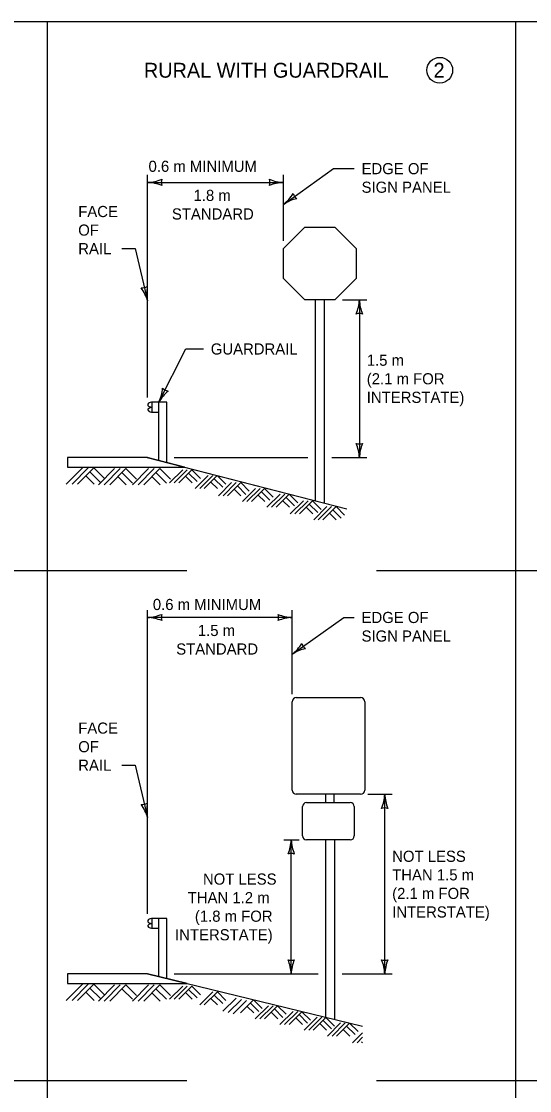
# Model space of a CAD drawing. Extents: x 49991.4 to 50021, y 49987.6 to 50011.4.
# Drawn here: x 50003.09 to 50005.83, y 49993.24 to 49999 of the extents above; entities that cross this region are included whole.
import ezdxf

# ---------------------------------------------------------------- set-up
doc = ezdxf.new("R2010")
doc.units = 0
for name, color, linetype in [('Level 1', 7, 'Continuous'), ('Level 2', 7, 'Continuous'), ('Level 3', 7, 'Continuous')]:
    doc.layers.add(name, color=color, linetype=linetype)

msp = doc.modelspace()

# ---------------------------------------------------------------- linework, layer by layer
at = {"layer": 'Level 1'}
for p, q in [((50004.6721, 49996.4167), (50004.6721, 49997.4987)), ((50004.7207, 49996.4043), (50004.7207, 49997.4987)), ((50003.8291, 49996.948), (50003.7885, 49996.948)), ((50003.7903, 49996.948), (50003.7903, 49996.8947)), ((50003.8291, 49996.6327), (50003.8291, 49996.948)), ((50003.872, 49996.948), (50003.8291, 49996.948)), ((50003.872, 49996.6219), (50003.872, 49996.948)), ((50003.7885, 49996.8947), (50003.8291, 49996.8947)), ((50003.768, 49996.649), (50003.336, 49996.649)), ((50003.336, 49996.649), (50003.336, 49996.5973)), ((50003.7649, 49996.649), (50003.336, 49996.649)), ((50003.336, 49996.649), (50003.336, 49996.5973)), ((50003.7649, 49996.649), (50004.8425, 49996.3731)), ((50003.9668, 49996.5973), (50003.7649, 49996.649)), ((50003.3298, 49996.5067), (50003.4171, 49996.5941)), ((50003.336, 49996.5973), (50003.9668, 49996.5973)), ((50003.336, 49996.5973), (50003.9668, 49996.5973)), ((50003.3605, 49996.5067), (50003.4478, 49996.5941)), ((50003.3909, 49996.5067), (50003.4782, 49996.5941)), ((50003.4568, 49996.5725), (50003.5135, 49996.5158)), ((50003.4782, 49996.5941), (50003.5351, 49996.5373)), ((50003.5026, 49996.5031), (50003.5899, 49996.5904)), ((50003.5333, 49996.5031), (50003.6206, 49996.5904)), ((50003.5637, 49996.5031), (50003.6511, 49996.5904)), ((50003.6295, 49996.5688), (50003.6862, 49996.5122)), ((50003.6511, 49996.5904), (50003.7079, 49996.5337)), ((50003.6861, 49996.5031), (50003.7734, 49996.5904)), ((50003.7168, 49996.5031), (50003.8041, 49996.5904)), ((50003.7472, 49996.5031), (50003.8346, 49996.5904)), ((50003.813, 49996.5688), (50003.8697, 49996.5122)), ((50003.8346, 49996.5904), (50003.8914, 49996.5337)), ((50003.8863, 49996.5126), (50003.957, 49996.5833)), ((50003.9112, 49996.5126), (50003.9819, 49996.5833)), ((50003.9358, 49996.5126), (50004.0065, 49996.5833)), ((50003.9665, 49996.5973), (50003.9665, 49996.5973)), ((50003.9665, 49996.5973), (50003.9665, 49996.5973)), ((50003.9668, 49996.5973), (50004.8425, 49996.3731)), ((50003.9891, 49996.5659), (50004.0352, 49996.52)), ((50004.0065, 49996.5833), (50004.0526, 49996.5373)), ((50003.4351, 49996.5508), (50003.4792, 49996.5067)), ((50003.6079, 49996.5471), (50003.652, 49996.5031)), ((50003.7914, 49996.5471), (50003.8355, 49996.5031)), ((50003.9716, 49996.5483), (50004.0075, 49996.5126)), ((50004.0238, 49996.4819), (50004.0945, 49996.5526)), ((50004.0486, 49996.4819), (50004.1193, 49996.5526)), ((50004.0732, 49996.4819), (50004.1435, 49996.552)), ((50004.109, 49996.5175), (50004.1449, 49996.4819)), ((50004.1266, 49996.5352), (50004.1726, 49996.4893)), ((50004.145, 49996.5517), (50004.19, 49996.5066)), ((50004.1495, 49996.4436), (50004.2202, 49996.5143)), ((50004.1744, 49996.4436), (50004.2451, 49996.5143)), ((50004.199, 49996.4436), (50004.2697, 49996.5143)), ((50004.2697, 49996.5143), (50004.3158, 49996.4683)), ((50004.2348, 49996.4793), (50004.2706, 49996.4436)), ((50004.2524, 49996.4969), (50004.2983, 49996.451)), ((50004.2786, 49996.4118), (50004.3493, 49996.4826)), ((50004.3035, 49996.4118), (50004.3743, 49996.4826)), ((50004.3282, 49996.4118), (50004.3989, 49996.4826)), ((50004.3639, 49996.4474), (50004.3997, 49996.4118)), ((50004.3814, 49996.4651), (50004.4274, 49996.4192)), ((50004.3989, 49996.4826), (50004.445, 49996.4365)), ((50004.4114, 49996.3813), (50004.4821, 49996.452)), ((50004.4362, 49996.3813), (50004.5071, 49996.452)), ((50004.461, 49996.3813), (50004.5317, 49996.452)), ((50004.5317, 49996.452), (50004.5778, 49996.4062)), ((50004.4967, 49996.417), (50004.5324, 49996.3813)), ((50004.5142, 49996.4346), (50004.5602, 49996.3889)), ((50004.5369, 49996.3456), (50004.6076, 49996.4164)), ((50004.5619, 49996.3456), (50004.6326, 49996.4164)), ((50004.5864, 49996.3456), (50004.6571, 49996.4164)), ((50004.6396, 49996.3989), (50004.6857, 49996.353)), ((50004.6571, 49996.4164), (50004.7033, 49996.3703)), ((50004.6631, 49996.3145), (50004.7338, 49996.3852)), ((50004.688, 49996.3145), (50004.7588, 49996.3852)), ((50004.7126, 49996.3145), (50004.7834, 49996.3852)), ((50004.7834, 49996.3852), (50004.8295, 49996.3393)), ((50004.6221, 49996.3813), (50004.6579, 49996.3456)), ((50004.7485, 49996.3502), (50004.7842, 49996.3145)), ((50004.766, 49996.3678), (50004.812, 49996.3219)), ((50004.5694, 49995.3563), (50004.9155, 49995.3563)), ((50004.5469, 49994.8576), (50004.5469, 49995.3338)), ((50004.938, 49995.3338), (50004.938, 49994.8576)), ((50004.9155, 49994.8351), (50004.5694, 49994.8351)), ((50004.728, 49994.7902), (50004.728, 49994.8351)), ((50004.7742, 49994.7902), (50004.7742, 49994.8351)), ((50004.6245, 49994.7902), (50004.8605, 49994.7902)), ((50004.603, 49994.611), (50004.603, 49994.7687)), ((50004.882, 49994.7687), (50004.882, 49994.611)), ((50004.8605, 49994.5895), (50004.6245, 49994.5895)), ((50004.728, 49993.6337), (50004.728, 49994.5895)), ((50004.7766, 49993.6218), (50004.7766, 49994.5895)), ((50003.829, 49994.1664), (50003.7884, 49994.1664)), ((50003.7902, 49994.1664), (50003.7902, 49994.1131)), ((50003.829, 49993.8511), (50003.829, 49994.1664)), ((50003.8719, 49994.1664), (50003.829, 49994.1664)), ((50003.8719, 49993.8403), (50003.8719, 49994.1664)), ((50003.7884, 49994.1131), (50003.829, 49994.1131)), ((50003.768, 49993.8673), (50003.336, 49993.8673)), ((50003.336, 49993.8673), (50003.336, 49993.8156)), ((50003.768, 49993.8673), (50003.336, 49993.8673)), ((50003.336, 49993.8673), (50003.336, 49993.8156)), ((50003.768, 49993.8673), (50004.9267, 49993.5853)), ((50003.9804, 49993.8156), (50003.768, 49993.8673)), ((50003.3299, 49993.725), (50003.4172, 49993.8124)), ((50003.336, 49993.8156), (50003.9804, 49993.8156)), ((50003.336, 49993.8156), (50003.9804, 49993.8156)), ((50003.3605, 49993.725), (50003.4479, 49993.8124)), ((50003.391, 49993.725), (50003.4783, 49993.8124)), ((50003.4783, 49993.8124), (50003.5352, 49993.7556)), ((50003.5027, 49993.7214), (50003.59, 49993.8087)), ((50003.5334, 49993.7214), (50003.6207, 49993.8087)), ((50003.5638, 49993.7214), (50003.6511, 49993.8087)), ((50003.6511, 49993.8087), (50003.708, 49993.752)), ((50003.6862, 49993.7214), (50003.7735, 49993.8087)), ((50003.7169, 49993.7214), (50003.8042, 49993.8087)), ((50003.7473, 49993.7214), (50003.8346, 49993.8087)), ((50003.8346, 49993.8087), (50003.8915, 49993.752)), ((50003.8864, 49993.7309), (50003.9571, 49993.8016)), ((50003.9113, 49993.7309), (50003.982, 49993.8016)), ((50003.9359, 49993.7309), (50004.0066, 49993.8016)), ((50003.9666, 49993.8156), (50003.9666, 49993.8156)), ((50004.0066, 49993.8016), (50004.0527, 49993.7556)), ((50003.4351, 49993.7691), (50003.4793, 49993.725)), ((50003.4568, 49993.7908), (50003.5136, 49993.7341)), ((50003.6295, 49993.7871), (50003.6863, 49993.7305)), ((50003.7915, 49993.7654), (50003.8356, 49993.7214)), ((50003.813, 49993.7871), (50003.8698, 49993.7305)), ((50003.9717, 49993.7666), (50004.0076, 49993.7309)), ((50003.9891, 49993.7842), (50004.0352, 49993.7383)), ((50004.0487, 49993.7002), (50004.1194, 49993.7709)), ((50004.0733, 49993.7002), (50004.1441, 49993.7709)), ((50004.1091, 49993.7358), (50004.145, 49993.7002)), ((50004.1267, 49993.7535), (50004.1726, 49993.7076)), ((50004.1441, 49993.7709), (50004.1901, 49993.7249)), ((50004.1739, 49993.6666), (50004.2446, 49993.7373)), ((50004.2027, 49993.6589), (50004.2734, 49993.7296)), ((50004.2296, 49993.6532), (50004.3003, 49993.7239)), ((50004.2689, 49993.6569), (50004.3396, 49993.7277)), ((50004.3047, 49993.6927), (50004.3404, 49993.6569)), ((50004.3222, 49993.7103), (50004.3682, 49993.6643)), ((50004.3396, 49993.7277), (50004.3857, 49993.6817)), ((50004.3484, 49993.6252), (50004.4191, 49993.696)), ((50004.3734, 49993.6252), (50004.4441, 49993.696)), ((50004.398, 49993.6252), (50004.4687, 49993.696)), ((50004.4513, 49993.6785), (50004.4972, 49993.6326)), ((50004.4687, 49993.696), (50004.5148, 49993.6499)), ((50004.4338, 49993.6608), (50004.4696, 49993.6252)), ((50004.4812, 49993.5947), (50004.5519, 49993.6654)), ((50004.5061, 49993.5947), (50004.5769, 49993.6654)), ((50004.5308, 49993.5947), (50004.6001, 49993.664)), ((50004.5666, 49993.6304), (50004.6023, 49993.5947)), ((50004.5841, 49993.648), (50004.63, 49993.6023)), ((50004.6001, 49993.664), (50004.6461, 49993.6183)), ((50004.6112, 49993.5639), (50004.6819, 49993.6347)), ((50004.6361, 49993.5639), (50004.7069, 49993.6347)), ((50004.6606, 49993.5639), (50004.7293, 49993.6326)), ((50004.7293, 49993.6325), (50004.7755, 49993.5864)), ((50004.6964, 49993.5996), (50004.7322, 49993.5639)), ((50004.7139, 49993.6172), (50004.76, 49993.5713)), ((50004.7374, 49993.5328), (50004.8081, 49993.6035)), ((50004.7623, 49993.5328), (50004.8331, 49993.6035)), ((50004.7869, 49993.5328), (50004.8566, 49993.6024)), ((50004.8228, 49993.5685), (50004.8585, 49993.5328)), ((50004.8403, 49993.586), (50004.8862, 49993.5402)), ((50004.8566, 49993.6024), (50004.9026, 49993.5564)), ((50004.8728, 49993.4969), (50004.9267, 49993.5508)), ((50004.8977, 49993.4969), (50004.9267, 49993.5259)), ((50004.9222, 49993.4969), (50004.9267, 49993.5014))]:
    msp.add_line(p, q, dxfattribs=at)
for points in [[(49999.3835, 49998.9992), (50016.7501, 49998.9992), (50016.7501, 49987.7988), (49999.3835, 49987.7988)], [(50004.615, 49997.8908), (50004.7778, 49997.8908), (50004.8925, 49997.7761), (50004.8925, 49997.6134), (50004.7778, 49997.4987), (50004.615, 49997.4987), (50004.5004, 49997.6134), (50004.5004, 49997.7761)]]:
    msp.add_lwpolyline(points, close=True, dxfattribs=at)
for centre, radius, start, end in [((50004.5694, 49995.3338), 0.0225, 90, 180), ((50004.9155, 49995.3338), 0.0225, 0, 90), ((50004.5694, 49994.8576), 0.0225, 180, 270), ((50004.9155, 49994.8576), 0.0225, 270, 0), ((50004.6245, 49994.7687), 0.0215, 90, 180), ((50004.8605, 49994.7687), 0.0215, 0, 90), ((50004.6245, 49994.611), 0.0215, 180, 270), ((50004.8605, 49994.611), 0.0215, 270, 0)]:
    msp.add_arc(centre, radius, start, end, dxfattribs=at)
for points in [[(50003.7885, 49996.948), (50003.7698, 49996.9374), (50003.7694, 49996.9304), (50003.7885, 49996.9213), (50003.7892, 49996.9211), (50003.7694, 49996.9099), (50003.7698, 49996.9062), (50003.7885, 49996.8947)], [(50003.7884, 49994.1664), (50003.7697, 49994.1558), (50003.7693, 49994.1488), (50003.7884, 49994.1397), (50003.7891, 49994.1395), (50003.7693, 49994.1283), (50003.7697, 49994.1246), (50003.7884, 49994.1131)]]:
    msp.add_spline(points, degree=3, dxfattribs=at)
at = {"layer": 'Level 2'}
msp.add_line((50004.5004, 49997.8908), (50004.5004, 49997.8908), dxfattribs=at)
msp.add_circle((50005.3426, 49998.7359), 0.0693, dxfattribs=at)
at = {"layer": 'Level 3'}
for p, q in [((50003.2287, 49987.7988), (50003.2287, 49998.9992)), ((50005.7525, 49987.7988), (50005.7525, 49998.9992)), ((50003.768, 49996.9736), (50003.768, 49998.1717)), ((50004.5004, 49998.0135), (50004.7704, 49998.2058)), ((50004.5004, 49997.8161), (50004.5004, 49998.1717)), ((50004.7704, 49998.2058), (50004.8812, 49998.2058)), ((50003.768, 49998.1317), (50004.5004, 49998.1317)), ((50003.6292, 49997.7749), (50003.7012, 49997.7749)), ((50003.7012, 49997.7749), (50003.768, 49997.4934)), ((50004.8178, 49997.4987), (50004.9493, 49997.4987)), ((50004.9093, 49997.4987), (50004.9093, 49996.649)), ((50003.8291, 49996.948), (50003.9743, 49997.2343)), ((50003.9743, 49997.2343), (50004.0685, 49997.2343)), ((50003.912, 49996.649), (50004.6321, 49996.649)), ((50004.7607, 49996.649), (50004.9493, 49996.649)), ((50002.4787, 49996.0407), (50003.9787, 49996.0407)), ((50005.0025, 49996.0407), (50006.5025, 49996.0407)), ((50003.768, 49994.1919), (50003.768, 49995.8278)), ((50004.5469, 49995.3738), (50004.5469, 49995.8278)), ((50004.5469, 49995.7878), (50003.768, 49995.7878)), ((50004.5469, 49995.5893), (50004.8257, 49995.7878)), ((50004.8257, 49995.7878), (50004.8811, 49995.7878)), ((50003.6292, 49994.9917), (50003.7012, 49994.9917)), ((50003.7012, 49994.9917), (50003.768, 49994.7102)), ((50004.9555, 49994.8351), (50005.0862, 49994.8351)), ((50005.0462, 49993.8673), (50005.0462, 49994.8351)), ((50004.502, 49994.5895), (50004.5845, 49994.5895)), ((50004.542, 49993.8673), (50004.542, 49994.5895)), ((50003.9119, 49993.8673), (50004.688, 49993.8673)), ((50004.8166, 49993.8673), (50005.0862, 49993.8673)), ((50002.4787, 49993.2934), (50003.9787, 49993.2934)), ((50005.0025, 49993.2934), (50006.5025, 49993.2934))]:
    msp.add_line(p, q, dxfattribs=at)
for centre, radius, start, end in [((50003.7565, 49998.3644), 0.233, 272.82731, 292.07716), ((50003.7588, 49997.9096), 0.2223, 67.45601, 87.63952), ((50003.8962, 49998.1317), 0.0548, 162.13882, 197.86118), ((50004.5096, 49998.3538), 0.2223, 247.45601, 267.63952), ((50004.3722, 49998.1317), 0.0548, 342.13882, 17.86118), ((50004.5119, 49997.899), 0.233, 92.82731, 112.07716), ((50004.356, 49998.1964), 0.233, 308.28663, 327.53647), ((50004.6048, 49998.0879), 0.0548, 197.59813, 233.32049), ((50004.6218, 49997.8273), 0.2223, 102.91533, 123.09883), ((50003.7376, 49997.618), 0.0548, 265.84975, 301.57211), ((50003.5446, 49997.4271), 0.233, 16.53824, 35.78809), ((50003.986, 49997.5372), 0.2223, 171.16694, 191.35045), ((50004.6872, 49997.5079), 0.2223, 337.45601, 357.63952), ((50005.142, 49997.5102), 0.233, 182.82731, 202.07716), ((50004.9093, 49997.3705), 0.0548, 72.13882, 107.86118), ((50003.617, 49997.0445), 0.233, 335.53959, 354.78944), ((50003.8879, 49997.0619), 0.0548, 224.8511, 260.57346), ((50004.0223, 49996.838), 0.2223, 130.16829, 150.3518), ((50004.9093, 49996.7772), 0.0548, 252.13882, 287.86118), ((50004.6766, 49996.6375), 0.233, 2.82731, 22.07716), ((50005.1314, 49996.6398), 0.2223, 157.45601, 177.63952), ((50003.7565, 49996.0205), 0.233, 272.82731, 292.07716), ((50003.7588, 49995.5657), 0.2223, 67.45601, 87.63952), ((50003.8962, 49995.7878), 0.0548, 162.13882, 197.86118), ((50004.5561, 49996.0099), 0.2223, 247.45601, 267.63952), ((50004.4187, 49995.7878), 0.0548, 342.13882, 17.86118), ((50004.5584, 49995.5551), 0.233, 92.82731, 112.07716), ((50004.4026, 49995.7722), 0.233, 308.27741, 327.52726), ((50004.6513, 49995.6637), 0.0548, 197.58892, 233.31128), ((50004.6683, 49995.403), 0.2223, 102.90611, 123.08962), ((50004.8241, 49994.8443), 0.2223, 337.45601, 357.63952), ((50005.2789, 49994.8466), 0.233, 182.82731, 202.07716), ((50003.7376, 49994.8348), 0.0548, 265.84975, 301.57211), ((50003.5446, 49994.6439), 0.233, 16.53824, 35.78809), ((50003.986, 49994.754), 0.2223, 171.16694, 191.35045), ((50005.0462, 49994.7069), 0.0548, 72.13882, 107.86118), ((50004.3199, 49994.5987), 0.2223, 337.45601, 357.63952), ((50004.7747, 49994.601), 0.233, 182.82731, 202.07716), ((50004.542, 49994.4613), 0.0548, 72.13882, 107.86118), ((50004.542, 49993.9955), 0.0548, 252.13882, 287.86118), ((50004.3093, 49993.8558), 0.233, 2.82731, 22.07716), ((50004.7641, 49993.8581), 0.2223, 157.45601, 177.63952), ((50005.0462, 49993.9955), 0.0548, 252.13882, 287.86118), ((50004.8135, 49993.8558), 0.233, 2.82731, 22.07716), ((50005.2683, 49993.8581), 0.2223, 157.45601, 177.63952)]:
    msp.add_arc(centre, radius, start, end, dxfattribs=at)

# ---------------------------------------------------------------- texts
at = {"layer": 'Level 2'}
for s, height, p in [('RURAL WITH GUARDRAIL', 0.08, (50003.748, 49998.6959)), ('2', 0.08, (50005.3091, 49998.6959)), ('0.6 m MINIMUM', 0.06, (50003.773, 49998.1885)), ('EDGE OF', 0.06, (50004.9212, 49998.1758)), ('SIGN PANEL', 0.06, (50004.9212, 49998.0758)), ('1.8 m', 0.06, (50004.0155, 49998.0317)), ('FACE', 0.06, (50003.3941, 49997.9449)), ('STANDARD', 0.06, (50003.899, 49997.9317)), ('OF', 0.06, (50003.3941, 49997.8449)), ('RAIL', 0.06, (50003.3941, 49997.7449)), ('GUARDRAIL', 0.06, (50004.1085, 49997.2043)), ('1.5 m', 0.06, (50004.9493, 49997.1438)), ('(2.1 m FOR', 0.06, (50004.9493, 49997.0438)), ('INTERSTATE)', 0.06, (50004.9493, 49996.9438)), ('0.6 m MINIMUM', 0.06, (50003.7963, 49995.8278)), ('EDGE OF', 0.06, (50004.9211, 49995.7578)), ('1.5 m', 0.06, (50004.0387, 49995.6878)), ('SIGN PANEL', 0.06, (50004.9211, 49995.6578)), ('STANDARD', 0.06, (50003.9222, 49995.5878)), ('FACE', 0.06, (50003.3941, 49995.1617)), ('OF', 0.06, (50003.3941, 49995.0617)), ('RAIL', 0.06, (50003.3941, 49994.9617)), ('NOT LESS', 0.06, (50005.0862, 49994.4712)), ('THAN 1.5 m', 0.06, (50005.0862, 49994.3712)), ('NOT LESS', 0.06, (50004.0663, 49994.3484)), ('(2.1 m FOR', 0.06, (50005.0862, 49994.2712)), ('THAN 1.2 m', 0.06, (50003.9843, 49994.2484)), ('(1.8 m FOR', 0.06, (50004.0227, 49994.1484)), ('INTERSTATE)', 0.06, (50005.0862, 49994.1712)), ('INTERSTATE)', 0.06, (50003.9159, 49994.0484))]:
    msp.add_text(s, height=height, dxfattribs=at).set_placement(p)

doc.saveas('drawing.dxf')
